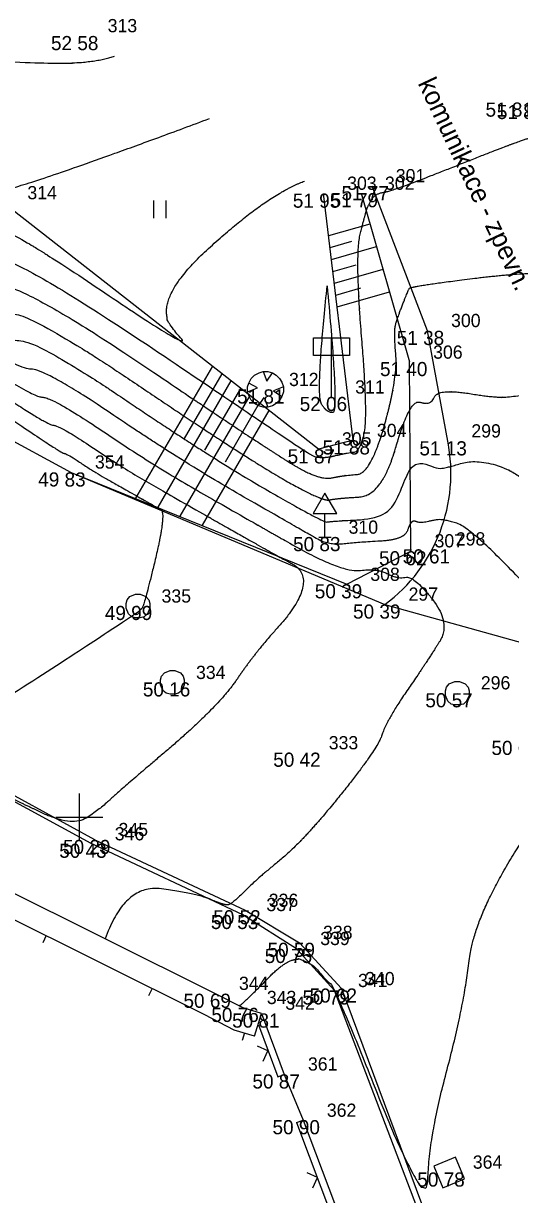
# Model space of a CAD drawing. Extents: x -704017 to -701500, y -1008977 to -1008450.
# Drawn here: x -704001.18 to -703990.87, y -1008658 to -1008633.17 of the extents above; entities that cross this region are included whole.
import ezdxf

# ---------------------------------------------------------------- set-up
doc = ezdxf.new("R2010")
doc.units = 0
for name, color, linetype in [('Z_body', 7, 'Continuous'), ('Z_body_cisla', 7, 'Continuous'), ('Z_body_vysky', 7, 'Continuous'), ('Z_dopravni_znaceni', 7, 'Continuous'), ('Z_hekt_sit', 7, 'Continuous'), ('Z_komunikace', 7, 'Continuous'), ('Z_obruby', 7, 'Continuous'), ('Z_popis', 7, 'Continuous'), ('Z_site_znaky_kanalizace', 7, 'Continuous'), ('Z_site_znaky_vodovod', 7, 'Continuous'), ('Z_teren_hrany_paty', 7, 'Continuous'), ('Z_vrstevnice_hlavni', 7, 'Continuous'), ('Z_vrstevnice_vedlejsi', 7, 'Continuous'), ('Z_vstupy', 7, 'Continuous'), ('Z_zelen_jednotliva', 7, 'Continuous')]:
    doc.layers.add(name, color=color, linetype=linetype)

# ---------------------------------------------------------------- blocks, each defined once
blk = doc.blocks.new('POINT_DISPLAY')
blk.add_line((0, 0), (0, 0))
blk = doc.blocks.new('Z210')
blk.add_line((0, 0), (0, 0.17))
blk = doc.blocks.new('Z212')
for p, q in [((-0.17, 0.17), (0, 0)), ((0, 0), (0.17, 0.17))]:
    blk.add_line(p, q)
blk = doc.blocks.new('Z306')
for p, q in [((-0.13, 0.17), (-0.13, -0.2)), ((0.13, 0.17), (0.13, -0.2))]:
    blk.add_line(p, q)
blk = doc.blocks.new('Z23')
for p, q in [((-0.3, 0.23), (-0.23, 0.3)), ((-0.23, 0.3), (-0.13, 0.35)), ((-0.13, 0.35), (-0.05, 0.38)), ((-0.05, 0.38), (0.05, 0.38)), ((-0.05, 0.38), (0.03, 0.17)), ((0.03, 0.17), (0.15, 0.35)), ((0.05, 0.38), (0.15, 0.35)), ((0.15, 0.35), (0.23, 0.3)), ((0.23, 0.3), (0.3, 0.23)), ((-0.38, 0.05), (-0.35, 0.13)), ((-0.38, -0.05), (-0.38, 0.05)), ((-0.38, -0.05), (-0.17, 0.03)), ((-0.35, 0.13), (-0.3, 0.23)), ((-0.17, 0.03), (-0.35, 0.13)), ((0.38, 0.05), (0.17, -0.03)), ((0.3, 0.23), (0.35, 0.15)), ((0.35, 0.15), (0.38, 0.05)), ((0.38, 0.05), (0.38, -0.05)), ((-0.35, -0.13), (-0.38, -0.05)), ((-0.3, -0.23), (-0.35, -0.13)), ((-0.23, -0.3), (-0.3, -0.23)), ((-0.15, -0.35), (-0.03, -0.17)), ((-0.03, -0.17), (0.05, -0.38)), ((0.17, -0.03), (0.35, -0.15)), ((0.3, -0.23), (0.23, -0.3)), ((0.35, -0.15), (0.3, -0.23)), ((0.38, -0.05), (0.35, -0.15)), ((-0.15, -0.35), (-0.23, -0.3)), ((-0.05, -0.38), (-0.15, -0.35)), ((0.05, -0.38), (-0.05, -0.38)), ((0.15, -0.35), (0.05, -0.38)), ((0.23, -0.3), (0.15, -0.35))]:
    blk.add_line(p, q)
blk = doc.blocks.new('Z527')
for p, q in [((0, 0.93), (-0.25, 0.5)), ((0.25, 0.5), (0, 0.93)), ((-0.25, 0.5), (0.25, 0.5)), ((0, 0), (0, 0.5)), ((-0.13, 0), (0.13, 0))]:
    blk.add_line(p, q)
blk = doc.blocks.new('Z57')
for p, q in [((-0.38, 1.25), (0.38, 1.25)), ((-0.38, 0.88), (-0.38, 1.25)), ((0, 0), (0, 1.25)), ((0.38, 1.25), (0.38, 0.88)), ((0.38, 0.88), (-0.38, 0.88))]:
    blk.add_line(p, q)
blk = doc.blocks.new('Z620')
for p, q in [((-0.17, 0.2), (-0.05, 0.25)), ((-0.05, 0.25), (0.05, 0.25)), ((0.05, 0.25), (0.17, 0.2)), ((-0.25, 0.05), (-0.23, 0.13)), ((-0.25, -0.05), (-0.25, 0.05)), ((-0.23, 0.13), (-0.17, 0.2)), ((0.17, 0.2), (0.23, 0.13)), ((0.23, 0.13), (0.25, 0.05)), ((0.25, 0.05), (0.25, -0.05)), ((-0.2, -0.17), (-0.25, -0.05)), ((-0.13, -0.23), (-0.2, -0.17)), ((-0.05, -0.25), (-0.13, -0.23)), ((0.13, -0.23), (0.05, -0.25)), ((0.2, -0.17), (0.13, -0.23)), ((0.25, -0.05), (0.2, -0.17)), ((0.05, -0.25), (-0.05, -0.25))]:
    blk.add_line(p, q)
blk = doc.blocks.new('Z608')
for p, q in [((0.25, 0.25), (-0.25, 0.25)), ((-0.25, 0.25), (-0.25, -0.25)), ((0.25, -0.25), (0.25, 0.25)), ((-0.25, -0.25), (0.25, -0.25))]:
    blk.add_line(p, q)

msp = doc.modelspace()

# ---------------------------------------------------------------- linework, layer by layer
at = {"layer": 'Z_hekt_sit'}
for p, q in [((-704000, -1008649.5), (-704000, -1008650.5)), ((-704000.5, -1008650), (-703999.5, -1008650))]:
    msp.add_line(p, q, dxfattribs=at)
at = {"layer": 'Z_komunikace'}
for p, q in [((-703992.63, -1008639.69), (-703993.8, -1008636.62)), ((-703992.2, -1008642.03), (-703992.63, -1008639.69)), ((-704005.01, -1008640.07), (-704000.17, -1008642.69)), ((-704000.17, -1008642.69), (-703993.53, -1008645.49)), ((-703993.53, -1008645.49), (-703988.96, -1008646.77)), ((-703999.67, -1008650.48), (-704008.03, -1008645.89)), ((-703999.67, -1008650.48), (-703996.49, -1008651.97)), ((-703996.49, -1008651.97), (-703995.34, -1008652.66)), ((-703995.34, -1008652.66), (-703994.45, -1008653.63)), ((-703994.45, -1008653.63), (-703992.64, -1008658.49))]:
    msp.add_line(p, q, dxfattribs=at)
msp.add_arc((-703995.6, -1008642.71), 3.467, 306.6532, 11.294, dxfattribs=at)
at = {"layer": 'Z_obruby'}
for p, q in [((-703999.75, -1008650.56), (-704008.13, -1008645.99)), ((-703996.54, -1008652.07), (-703999.75, -1008650.56)), ((-703995.4, -1008652.79), (-703996.54, -1008652.07)), ((-703994.6, -1008653.67), (-703995.4, -1008652.79)), ((-703992.74, -1008658.56), (-703994.6, -1008653.67))]:
    msp.add_line(p, q, dxfattribs=at)
at = {"layer": 'Z_teren_hrany_paty'}
for p, q in [((-703994.2, -1008642.01), (-703994.83, -1008636.78)), ((-703994.03, -1008636.77), (-703993.01, -1008640.35)), ((-703994.94, -1008642.2), (-704001.6, -1008636.98)), ((-703994.72, -1008637.67), (-703993.84, -1008637.42)), ((-703994.69, -1008637.92), (-703994.23, -1008637.79)), ((-703994.66, -1008638.18), (-703993.71, -1008637.9)), ((-703994.63, -1008638.43), (-703994.14, -1008638.29)), ((-703994.6, -1008638.68), (-703993.57, -1008638.38)), ((-703994.57, -1008638.93), (-703994.04, -1008638.78)), ((-703994.54, -1008639.18), (-703993.43, -1008638.86)), ((-703992.98, -1008644.36), (-703993.01, -1008640.35)), ((-703997.18, -1008640.44), (-703998.81, -1008643.24)), ((-703996.98, -1008640.6), (-703997.78, -1008641.97)), ((-703996.79, -1008640.75), (-703998.34, -1008643.43)), ((-703996.39, -1008641.06), (-703997.87, -1008643.62)), ((-703996.59, -1008640.91), (-703997.35, -1008642.22)), ((-703995.99, -1008641.38), (-703997.4, -1008643.81)), ((-703996.19, -1008641.22), (-703996.91, -1008642.47)), ((-703994.2, -1008642.01), (-703994.94, -1008642.2)), ((-704000.17, -1008642.69), (-703994.34, -1008645.06)), ((-703994.34, -1008645.06), (-703992.98, -1008644.36)), ((-703997.12, -1008653.74), (-704004.85, -1008649.89)), ((-703997.34, -1008654.19), (-704005.09, -1008650.33)), ((-703996.53, -1008654.04), (-703997.12, -1008653.74)), ((-703996.14, -1008654.16), (-703996.53, -1008654.04)), ((-703996.72, -1008654.51), (-703997.34, -1008654.19)), ((-703996.29, -1008654.64), (-703996.14, -1008654.16)), ((-703996.14, -1008654.16), (-703995.66, -1008655.45)), ((-703996.29, -1008654.64), (-703996.72, -1008654.51)), ((-703996.21, -1008654.4), (-703995.8, -1008655.5)), ((-703995.8, -1008655.5), (-703995.66, -1008655.45)), ((-703995.4, -1008656.47), (-703995.26, -1008656.42)), ((-703995.4, -1008656.47), (-703992.45, -1008664.3)), ((-703995.26, -1008656.42), (-703992.31, -1008664.25))]:
    msp.add_line(p, q, dxfattribs=at)
at = {"layer": 'Z_vrstevnice_hlavni'}
for points in [[(-704008.891, -1008633.225), (-704007.19, -1008634.58), (-704001.968, -1008637.528), (-704001.463, -1008637.527), (-703997.345, -1008640.315), (-703998.566, -1008639.143), (-703996.039, -1008636.816), (-703995.232, -1008636.515)], [(-704009.834, -1008633.947), (-704008.639, -1008634.898), (-704007.097, -1008636.135), (-704003.977, -1008638.277), (-704003.231, -1008638.819), (-704001.631, -1008639.907), (-704000.867, -1008639.906), (-703997.17, -1008642.409), (-703994.823, -1008643.756), (-703994.703, -1008643.728), (-703993.348, -1008643.651), (-703992.995, -1008642.406), (-703992.399, -1008642.624), (-703992.166, -1008642.575), (-703991.657, -1008642.421), (-703990.877, -1008642.602), (-703990.087, -1008643.243), (-703988.737, -1008643.725), (-703987.719, -1008644.81), (-703986.755, -1008645.399), (-703986.308, -1008645.619), (-703984.807, -1008646.186), (-703985.704, -1008645.225), (-703986.427, -1008644.081), (-703986.268, -1008643.227), (-703985.558, -1008644.406), (-703985.308, -1008644.79), (-703982.136, -1008647.335), (-703982.104, -1008647.377), (-703980.996, -1008647.981), (-703981.138, -1008648.096), (-703981.236, -1008648.238), (-703982.91, -1008647.991), (-703984.29, -1008649.466), (-703985.783, -1008651.25), (-703985.074, -1008654.306), (-703985.408, -1008655.307), (-703984.22, -1008656.692), (-703983.2, -1008656.858), (-703982.505, -1008657.462), (-703981.889, -1008657.948), (-703981.945, -1008658.047), (-703982.027, -1008658.206), (-703982.128, -1008658.577), (-703982.119, -1008658.578), (-703981.97, -1008658.325), (-703981.459, -1008658.081), (-703981.513, -1008658.577), (-703981.415, -1008659.217), (-703981.332, -1008659.732), (-703980.559, -1008660.215), (-703980.405, -1008660.435), (-703979.463, -1008659.63), (-703979.059, -1008659.888), (-703977.693, -1008660.229), (-703973.778, -1008660.657)], [(-704010.777, -1008634.669), (-704010.089, -1008635.217), (-704007.004, -1008637.69), (-704006.178, -1008638.257), (-704004.336, -1008639.596), (-704000.382, -1008642.286), (-704000.271, -1008642.286), (-703999.734, -1008642.649), (-703999.257, -1008642.923), (-703998.4, -1008643.409), (-703998.154, -1008643.54), (-703998.629, -1008645.519), (-703998.717, -1008645.615), (-703998.79, -1008645.685), (-704003.184, -1008648.551), (-704004.04, -1008648.141), (-704004.898, -1008647.753), (-704005.446, -1008649.181), (-704005.674, -1008649.406)], [(-703994.753, -1008638.739), (-703994.996, -1008641.052), (-703994.748, -1008641.441), (-703994.507, -1008641.397), (-703994.753, -1008638.739)]]:
    msp.add_open_spline(points, degree=2, dxfattribs=at)
at = {"layer": 'Z_vrstevnice_vedlejsi'}
for points in [[(-704008.419, -1008632.864), (-704008.353, -1008632.917), (-704007.931, -1008633.135), (-704000.289, -1008634.249), (-703999.256, -1008633.864)], [(-704008.655, -1008633.045), (-704007.772, -1008633.748), (-704002.069, -1008636.695), (-704001.503, -1008636.778), (-703997.244, -1008635.19)], [(-704009.126, -1008633.406), (-704007.552, -1008634.66), (-704007.167, -1008634.969), (-704003.51, -1008637.478), (-704002.368, -1008638.123), (-704001.314, -1008638.122), (-703995.248, -1008642.229), (-703994.924, -1008642.415), (-703994.274, -1008642.264), (-703994.074, -1008642.252), (-703993.878, -1008641.56), (-703994.168, -1008638.078), (-703993.925, -1008637.137), (-703993.893, -1008637.055), (-703993.74, -1008636.777), (-703993.37, -1008636.731), (-703990.438, -1008635.556), (-703990.255, -1008635.594), (-703990.156, -1008635.607), (-703988.632, -1008637.37), (-703988.058, -1008638.31), (-703987.723, -1008639.127), (-703986.345, -1008641.268), (-703986.112, -1008641.639), (-703985.122, -1008643.283), (-703983.979, -1008645.038), (-703982.267, -1008646.413), (-703982.073, -1008646.661), (-703980.768, -1008647.373), (-703978.866, -1008647.6), (-703973.038, -1008648.345), (-703968.556, -1008648.679), (-703966.324, -1008648.776), (-703962.321, -1008649.227), (-703959.855, -1008649.621), (-703958.687, -1008649.76), (-703957.02, -1008650.02), (-703953.686, -1008650.359), (-703951.625, -1008650.597), (-703947.923, -1008651.012), (-703945.94, -1008651.178), (-703944.226, -1008651.1), (-703941.822, -1008651.374), (-703941.922, -1008651.3), (-703941.645, -1008651.165), (-703939.586, -1008650.472), (-703938.685, -1008649.995), (-703933.226, -1008648.754), (-703931.62, -1008648.491), (-703929.958, -1008648.552), (-703928.07, -1008648.165), (-703926.551, -1008646.817), (-703917.569, -1008646.632), (-703915.381, -1008647.242), (-703912.13, -1008647.203), (-703904.124, -1008647.793), (-703900.507, -1008648.357), (-703893.497, -1008649.743), (-703885.663, -1008650.277), (-703881.6, -1008650.754), (-703868.608, -1008650.262)], [(-704009.362, -1008633.586), (-704007.915, -1008634.739), (-704007.143, -1008635.358), (-704002.876, -1008638.286), (-704002.679, -1008638.43), (-704002.255, -1008638.718), (-704001.165, -1008638.717), (-703995.889, -1008642.289), (-703994.89, -1008642.862), (-703994.417, -1008642.752), (-703993.832, -1008642.719), (-703993.258, -1008640.696), (-703993.341, -1008639.701), (-703993.272, -1008639.432), (-703993.04, -1008638.835), (-703992.99, -1008638.745), (-703990.403, -1008638.423), (-703989.481, -1008638.539), (-703989.058, -1008638.588), (-703989.018, -1008638.516), (-703988.578, -1008638.54), (-703988.475, -1008638.554), (-703988.362, -1008638.685), (-703988.319, -1008638.754), (-703988.294, -1008638.815), (-703986.637, -1008641.391), (-703986.518, -1008641.581), (-703985.267, -1008643.657), (-703984.422, -1008644.955), (-703982.223, -1008646.72), (-703982.083, -1008646.9), (-703980.47, -1008647.779), (-703979.335, -1008647.914), (-703971.793, -1008648.878), (-703969.312, -1008649.063), (-703968.076, -1008649.117), (-703960.948, -1008649.919), (-703959.282, -1008650.186), (-703958.493, -1008650.28), (-703957.367, -1008650.455), (-703955.116, -1008650.684), (-703950.816, -1008651.182), (-703948.3, -1008651.463), (-703946.953, -1008651.576), (-703945.397, -1008651.505), (-703943.023, -1008651.703), (-703939.161, -1008651.987), (-703938.27, -1008652.079), (-703937.191, -1008652.194), (-703934.147, -1008651.524), (-703931.028, -1008650.815), (-703930.717, -1008650.764), (-703928.94, -1008650.83), (-703928.501, -1008650.751), (-703928.424, -1008650.713), (-703928.413, -1008650.708), (-703928.266, -1008650.724), (-703926.027, -1008648.737), (-703920.5, -1008648.624), (-703915.824, -1008649.925), (-703908.88, -1008649.843), (-703904.651, -1008650.155), (-703897.103, -1008651.333), (-703893.743, -1008651.997), (-703889.99, -1008652.252), (-703881.693, -1008653.228), (-703874.656, -1008652.961), (-703868.448, -1008652.365), (-703859.857, -1008652.906), (-703856.36, -1008653.001), (-703843.765, -1008653.766), (-703842.17, -1008653.801), (-703841.143, -1008653.824), (-703831.904, -1008654.28)], [(-704009.598, -1008633.766), (-704008.277, -1008634.819), (-704007.12, -1008635.746), (-704003.426, -1008638.282), (-704002.955, -1008638.624), (-704001.943, -1008639.313), (-704001.016, -1008639.312), (-703996.53, -1008642.349), (-703994.857, -1008643.309), (-703994.56, -1008643.24), (-703993.59, -1008643.185), (-703993.004, -1008641.121), (-703992.56, -1008641.283), (-703992.406, -1008640.907), (-703990.978, -1008641.146), (-703990.445, -1008640.984), (-703988.033, -1008641.546), (-703987.905, -1008641.575), (-703987.885, -1008641.539), (-703987.861, -1008641.54), (-703986.998, -1008641.406), (-703986.928, -1008641.515), (-703986.924, -1008641.522), (-703985.413, -1008644.031), (-703984.865, -1008644.873), (-703982.18, -1008647.028), (-703982.094, -1008647.138), (-703980.173, -1008648.185), (-703979.805, -1008648.229), (-703970.549, -1008649.412), (-703970.068, -1008649.448), (-703969.829, -1008649.458), (-703959.574, -1008650.612), (-703958.709, -1008650.75), (-703958.299, -1008650.799), (-703957.715, -1008650.89), (-703956.546, -1008651.009), (-703950.007, -1008651.766), (-703948.677, -1008651.914), (-703947.966, -1008651.974), (-703947.144, -1008651.937), (-703941.803, -1008652.381), (-703939.634, -1008652.541), (-703935.959, -1008652.918), (-703931.507, -1008653.392), (-703931.241, -1008653.334), (-703930.405, -1008652.729), (-703929.637, -1008652.341), (-703928.842, -1008651.433), (-703928.478, -1008651.254), (-703928.326, -1008651.185), (-703926.344, -1008651.403), (-703925.504, -1008650.658), (-703923.431, -1008650.615), (-703921.507, -1008651.151), (-703919.021, -1008652.183), (-703918.063, -1008652.174), (-703916.275, -1008652.677), (-703914.94, -1008652.463), (-703906.465, -1008652.493), (-703905.63, -1008652.483), (-703905.177, -1008652.517), (-703898.478, -1008653.562), (-703894.56, -1008654.198), (-703893.983, -1008654.291), (-703885.85, -1008655.223), (-703881.786, -1008655.701), (-703881.516, -1008655.691), (-703868.843, -1008654.474), (-703864.229, -1008654.765), (-703856.36, -1008654.976), (-703848.079, -1008655.479), (-703842.495, -1008655.602), (-703838.899, -1008655.683), (-703831.037, -1008656.071), (-703828.126, -1008656.326), (-703816.323, -1008657.511), (-703813.977, -1008657.649), (-703805.195, -1008657.724)], [(-703996.614, -1008653.997), (-703996.53, -1008653.954), (-703995.4, -1008652.79), (-703994.748, -1008653.468), (-703994.565, -1008653.661), (-703992.64, -1008658.49), (-703992.598, -1008656.799), (-703991.854, -1008653.994), (-703991.65, -1008652.14), (-703989.884, -1008649.309), (-703988.96, -1008646.77), (-703991.654, -1008643.898), (-703992.295, -1008643.669), (-703992.59, -1008643.726), (-703992.781, -1008643.766), (-703992.985, -1008643.692), (-703993.106, -1008644.118), (-703994.107, -1008644.174), (-703994.716, -1008644.242), (-703995.23, -1008643.95), (-703997.811, -1008642.469), (-704000.718, -1008640.501), (-704001.319, -1008640.502), (-704003.507, -1008639.013), (-704004.527, -1008638.272), (-704007.073, -1008636.524), (-704009.002, -1008634.978), (-704010.07, -1008634.127)], [(-704010.305, -1008634.308), (-704009.364, -1008635.058), (-704007.05, -1008636.913), (-704005.077, -1008638.267), (-704003.784, -1008639.207), (-704001.007, -1008641.096), (-704000.569, -1008641.096), (-703998.452, -1008642.529), (-703996.572, -1008643.608), (-703994.455, -1008644.81), (-703993.69, -1008644.725), (-703993.267, -1008644.95), (-703992.917, -1008644.879), (-703992.134, -1008645.881), (-703992.595, -1008646.639), (-703993.503, -1008647.958), (-703993.68, -1008648.547), (-703995.276, -1008650.526), (-703996.236, -1008651.302), (-703996.767, -1008651.84), (-703996.931, -1008651.871), (-703997.503, -1008651.617), (-703999.042, -1008651.416), (-703999.451, -1008652.579)], [(-704010.541, -1008634.488), (-704009.726, -1008635.137), (-704007.027, -1008637.301), (-704005.627, -1008638.262), (-704004.06, -1008639.402), (-704000.694, -1008641.691), (-704000.42, -1008641.691), (-703999.093, -1008642.589), (-703997.915, -1008643.265), (-703995.798, -1008644.468), (-703995.19, -1008644.79), (-703995.36, -1008645.501), (-703996.269, -1008646.494), (-703997.057, -1008647.656), (-703999.165, -1008649.452), (-703999.549, -1008649.819), (-704000.155, -1008650.214), (-704001.546, -1008649.547), (-704001.905, -1008649.385), (-704002.231, -1008650.234), (-704002.519, -1008651.051)]]:
    msp.add_open_spline(points, degree=2, dxfattribs=at)
at = {"layer": 'Z_vstupy'}
msp.add_line((-703995.66, -1008655.45), (-703995.26, -1008656.42), dxfattribs=at)

# ---------------------------------------------------------------- block references
at = {"layer": 'Z_body'}
for p in [(-703999.9, -1008633.44), (-703993.8, -1008636.62), (-703994.83, -1008636.78), (-703994.03, -1008636.77), (-703992.63, -1008639.69), (-703993.01, -1008640.35), (-703996.06, -1008640.93), (-703994.66, -1008641.09), (-703994.2, -1008642.01), (-703992.2, -1008642.03), (-703994.94, -1008642.2), (-704000.17, -1008642.69), (-703994.8, -1008644.06), (-703992.98, -1008644.36), (-703992.53, -1008644.32), (-703994.34, -1008645.06), (-703998.76, -1008645.52), (-703993.53, -1008645.49), (-703998.03, -1008647.14), (-703992, -1008647.37), (-703995.22, -1008648.63), (-703999.75, -1008650.56), (-703999.67, -1008650.48), (-703996.49, -1008651.97), (-703996.54, -1008652.07), (-703995.4, -1008652.79), (-703995.34, -1008652.66), (-703997.12, -1008653.74), (-703994.6, -1008653.67), (-703994.45, -1008653.63), (-703996.53, -1008654.04), (-703996.14, -1008654.16), (-703995.66, -1008655.45), (-703995.26, -1008656.42), (-703992.17, -1008657.53)]:
    msp.add_blockref('POINT_DISPLAY', p, dxfattribs=at)
at = {"layer": 'Z_dopravni_znaceni'}
for name, p in [('Z57', (-703994.66, -1008641.09)), ('Z527', (-703994.8, -1008644.06))]:
    msp.add_blockref(name, p, dxfattribs=at)
at = {"layer": 'Z_popis'}
msp.add_blockref('Z306', (-703998.3, -1008637.1), dxfattribs=at)
at = {"layer": 'Z_site_znaky_kanalizace'}
for p in [(-703998.76, -1008645.52), (-703998.03, -1008647.14), (-703992, -1008647.37)]:
    msp.add_blockref('Z620', p, dxfattribs=at)
at = {"layer": 'Z_site_znaky_vodovod', "rotation": -67.49999999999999}
msp.add_blockref('Z608', (-703992.17, -1008657.53), dxfattribs=at)
at = {"layer": 'Z_teren_hrany_paty'}
for name, p, rotation in [('Z210', (-704000.7, -1008652.51), 153.5), ('Z210', (-703998.46, -1008653.63), 153.5), ('Z210', (-703996.5, -1008654.57), 162.9), ('Z212', (-703996.01, -1008654.95), 110.40000000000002), ('Z212', (-703994.96, -1008657.64), 110.59999999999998)]:
    msp.add_blockref(name, p, dxfattribs=dict(at, rotation=rotation))
at = {"layer": 'Z_zelen_jednotliva'}
msp.add_blockref('Z23', (-703996.06, -1008640.93), dxfattribs=at)

# ---------------------------------------------------------------- texts
at = {"layer": 'Z_body_cisla'}
for s, p in [('313', (-703999.4, -1008633.36)), ('303', (-703994.33, -1008636.7)), ('302', (-703993.53, -1008636.7)), ('301', (-703993.3, -1008636.54)), ('314', (-704001.1, -1008636.9)), ('300', (-703992.13, -1008639.61)), ('306', (-703992.51, -1008640.28)), ('312', (-703995.56, -1008640.86)), ('311', (-703994.16, -1008641.02)), ('305', (-703994.44, -1008642.12)), ('304', (-703993.7, -1008641.94)), ('299', (-703991.7, -1008641.95)), ('354', (-703999.67, -1008642.61)), ('310', (-703994.3, -1008643.99)), ('307', (-703992.48, -1008644.28)), ('298', (-703992.03, -1008644.24)), ('308', (-703993.84, -1008644.99)), ('335', (-703998.26, -1008645.45)), ('297', (-703993.03, -1008645.41)), ('334', (-703997.53, -1008647.07)), ('296', (-703991.5, -1008647.29)), ('333', (-703994.72, -1008648.56)), ('346', (-703999.25, -1008650.49)), ('345', (-703999.17, -1008650.4)), ('337', (-703996.04, -1008651.99)), ('336', (-703995.99, -1008651.9)), ('338', (-703994.84, -1008652.58)), ('339', (-703994.9, -1008652.71)), ('340', (-703993.95, -1008653.56)), ('344', (-703996.62, -1008653.66)), ('341', (-703994.1, -1008653.6)), ('343', (-703996.03, -1008653.96)), ('342', (-703995.64, -1008654.08)), ('361', (-703995.16, -1008655.37)), ('362', (-703994.76, -1008656.35)), ('364', (-703991.67, -1008657.45))]:
    msp.add_text(s, height=0.28, dxfattribs=at).set_placement(p)
at = {"layer": 'Z_body_vysky'}
for s, p in [('52 58', (-704000.6, -1008633.74)), ('51 81', (-703991.4, -1008635.15)), ('51 81', (-703991.16, -1008635.2)), ('51 77', (-703994.45, -1008636.92)), ('51 95', (-703995.48, -1008637.08)), ('51 79', (-703994.68, -1008637.07)), ('51 38', (-703993.28, -1008639.99)), ('51 40', (-703993.635, -1008640.65)), ('51 81', (-703996.66, -1008641.23)), ('52 06', (-703995.335, -1008641.39)), ('51 88', (-703994.85, -1008642.31)), ('51 13', (-703992.8, -1008642.33)), ('51 87', (-703995.59, -1008642.5)), ('49 83', (-704000.87, -1008642.99)), ('50 83', (-703995.475, -1008644.36)), ('50 62', (-703993.655, -1008644.66)), ('50 61', (-703993.155, -1008644.62)), ('50 39', (-703995.015, -1008645.36)), ('49 99', (-703999.46, -1008645.82)), ('50 39', (-703994.205, -1008645.79)), ('50 16', (-703998.655, -1008647.44)), ('50 57', (-703992.675, -1008647.67)), ('50 66', (-703991.275, -1008648.68)), ('50 42', (-703995.895, -1008648.93)), ('50 43', (-704000.425, -1008650.86)), ('50 29', (-704000.345, -1008650.78)), ('50 52', (-703997.165, -1008652.27)), ('50 53', (-703997.215, -1008652.37)), ('50 75', (-703996.075, -1008653.09)), ('50 59', (-703996.015, -1008652.96)), ('50 69', (-703997.795, -1008654.04)), ('50 79', (-703995.275, -1008653.97)), ('50 62', (-703995.125, -1008653.93)), ('50 76', (-703997.205, -1008654.34)), ('50 81', (-703996.765, -1008654.46)), ('50 87', (-703996.335, -1008655.75)), ('50 90', (-703995.91, -1008656.72)), ('50 78', (-703992.845, -1008657.83))]:
    msp.add_text(s, height=0.3, dxfattribs=at).set_placement(p)
at = {"layer": 'Z_popis'}
msp.add_text('komunikace - zpevn.', height=0.4, rotation=295.2, dxfattribs=at).set_placement((-703992.84, -1008634.44))

doc.saveas('drawing.dxf')
